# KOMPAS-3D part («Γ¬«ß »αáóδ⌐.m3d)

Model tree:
1. Эскиз:1
2. Операция выдавливания:1
     Расстояние 1 = 0.5; Расстояние 2 = 1.1
3. Эскиз:10
4. Операция выдавливания:8
     Расстояние 1 = 2; Расстояние 2 = 1.1
5. Эскиз:11
6. Операция выдавливания:9
     Расстояние 1 = 2; Расстояние 2 = 1.1
7. Эскиз:12
8. Операция выдавливания:10
     Расстояние 1 = 8; Расстояние 2 = 1.1
9. Эскиз:13
10. Вырезать элемент выдавливания:2
     Расстояние 2 = 4; Расстояние 1 = 12.4454
11. Скругление:9
     Радиус = 0.5
12. Скругление:10
     Радиус = 0.5
13. Скругление:11
     Радиус = 0.5
14. Скругление:12
     Радиус = 0.5
15. Скругление:13
     Радиус = 0.2
16. Эскиз:14
17. Операция выдавливания:11
     Расстояние 1 = 0.5; Расстояние 2 = 1.1
18. Эскиз:15
19. Операция выдавливания:12
     Расстояние 1 = 0.3; Расстояние 2 = 1.1

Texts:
  Сплав АЛ8  ГОСТ 1583-93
